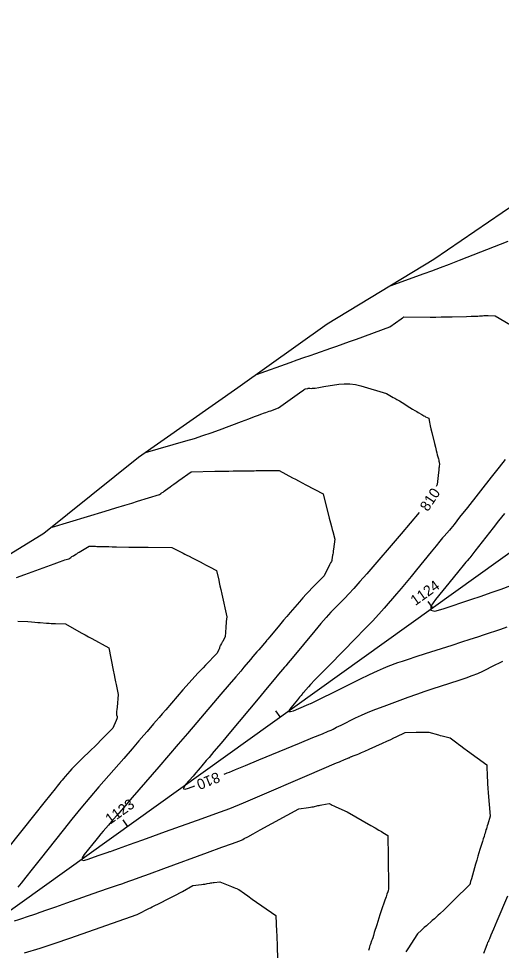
# Model space of a CAD drawing. Extents: x 2079879 to 2092887, y 778083 to 784051.
# Drawn here: x 2084202.5 to 2084331.2, y 781138.5 to 781386.8 of the extents above; entities that cross this region are included whole.
import ezdxf

# ---------------------------------------------------------------- set-up
doc = ezdxf.new("R2010")
doc.units = 0
for name, color, linetype in [('DT_X_Contour_Major', 7, 'Continuous'), ('DT_X_Contour_Minor', 7, 'Continuous'), ('DT_X_TIN_Hull', 7, 'Continuous'), ('GE_X_CL_20', 7, 'Continuous')]:
    doc.layers.add(name, color=color, linetype=linetype)

msp = doc.modelspace()

# ---------------------------------------------------------------- linework, layer by layer
at = {"layer": 'DT_X_Contour_Major'}
for points in [[(2084236.35, 781271.19), (2084247.11, 781274.26), (2084249.4, 781274.94), (2084251.66, 781275.67), (2084253.89, 781276.43), (2084256.09, 781277.24), (2084261.92, 781279.45), (2084263.88, 781280.19), (2084265.39, 781280.76), (2084266.45, 781281.16), (2084267.06, 781281.38), (2084268.07, 781281.74), (2084268.46, 781281.88), (2084268.87, 781282.02), (2084269.29, 781282.17), (2084269.73, 781282.33), (2084271.83, 781283.06), (2084277.36, 781287.05), (2084278.01, 781287.52), (2084278.42, 781287.82), (2084278.61, 781287.95), (2084278.92, 781288.18), (2084279.58, 781288.27), (2084279.73, 781288.29), (2084279.87, 781288.3), (2084280.02, 781288.3), (2084280.17, 781288.29), (2084280.56, 781288.26), (2084280.88, 781288.29), (2084281.53, 781288.37), (2084282.52, 781288.52), (2084283.85, 781288.73), (2084287.83, 781289.37), (2084289.32, 781289.52), (2084290.8, 781289.5), (2084292.28, 781289.32), (2084293.74, 781288.96), (2084300.58, 781286.88), (2084302.39, 781285.87), (2084302.83, 781285.62), (2084303.37, 781285.3), (2084304, 781284.93), (2084304.73, 781284.48), (2084306.81, 781283.21), (2084307.53, 781282.77), (2084308.15, 781282.39), (2084308.65, 781282.09), (2084309.04, 781281.85), (2084309.95, 781281.32), (2084310.27, 781281.13), (2084310.55, 781280.97), (2084310.79, 781280.84), (2084310.99, 781280.73), (2084311.83, 781280.3), (2084312.02, 781279.21), (2084312.09, 781278.86), (2084312.22, 781278.3), (2084312.4, 781277.53), (2084312.65, 781276.53), (2084313.37, 781273.6), (2084313.63, 781272.59), (2084313.83, 781271.75), (2084314, 781271.08), (2084314.12, 781270.58), (2084314.4, 781269.49), (2084314.49, 781269.12), (2084314.56, 781268.83), (2084314.61, 781268.62), (2084314.64, 781268.5), (2084314.73, 781268.11), (2084314.63, 781267.5), (2084314.6, 781267.3), (2084314.56, 781266.96), (2084314.5, 781266.48), (2084314.43, 781265.86), (2084314.05, 781262.63), (2084313.83, 781262.07)], [(2084309.24, 781255.14), (2084304.46, 781249.47), (2084295.31, 781238.86), (2084293.47, 781236.75), (2084291.88, 781234.96), (2084290.53, 781233.49), (2084289.44, 781232.34), (2084286.84, 781229.7), (2084285.77, 781228.58), (2084284.52, 781227.2), (2084283.09, 781225.55), (2084281.48, 781223.63), (2084275.45, 781216.38), (2084274.38, 781215.1), (2084273.74, 781214.33), (2084273.52, 781214.07), (2084273.52, 781214.06), (2084273.39, 781213.92), (2084272.37, 781212.74), (2084271.81, 781212.08), (2084270.62, 781210.66), (2084268.8, 781208.48), (2084266.34, 781205.54), (2084258.96, 781196.69), (2084256.48, 781193.73), (2084254.59, 781191.46), (2084253.28, 781189.9), (2084252.55, 781189.04), (2084251.39, 781187.67), (2084250.91, 781187.12), (2084250.36, 781186.48), (2084249.73, 781185.74), (2084249.03, 781184.93), (2084247.04, 781182.63), (2084246.53, 781181.92), (2084246.48, 781181.53), (2084246.9, 781181.45), (2084247.78, 781181.69), (2084249.52, 781182.3)], [(2084257.32, 781185.4), (2084257.51, 781185.48), (2084257.72, 781185.57), (2084258.11, 781185.74), (2084258.74, 781186), (2084260.36, 781186.67), (2084262.96, 781187.74), (2084266.53, 781189.22), (2084277.37, 781193.69), (2084280.93, 781195.16), (2084283.48, 781196.21), (2084285.02, 781196.85), (2084285.55, 781197.07), (2084285.6, 781197.09), (2084285.8, 781197.19), (2084286.35, 781197.46), (2084287.26, 781197.91), (2084288.51, 781198.53), (2084292.34, 781200.42), (2084293.9, 781201.15), (2084295.69, 781201.92), (2084297.72, 781202.74), (2084299.99, 781203.59), (2084306.36, 781205.92), (2084308.69, 781206.76), (2084310.89, 781207.54), (2084312.97, 781208.24), (2084314.92, 781208.88), (2084319.95, 781210.48), (2084321.76, 781211.08), (2084323.41, 781211.69), (2084324.9, 781212.3), (2084326.23, 781212.92), (2084329.55, 781214.56), (2084330.68, 781215.12), (2084331.57, 781215.56)], [(2084332.86, 781152.9), (2084330.01, 781146.26), (2084329.07, 781144.08), (2084328.4, 781142.5), (2084327.98, 781141.52), (2084327.83, 781141.15), (2084327.78, 781140.96), (2084327.76, 781140.89), (2084327.73, 781140.82), (2084327.69, 781140.76), (2084327.65, 781140.69), (2084327.51, 781140.52), (2084327.37, 781140.16), (2084327.02, 781139.18), (2084326.46, 781137.59)]]:
    msp.add_lwpolyline(points, dxfattribs=at)
at = {"layer": 'DT_X_Contour_Minor'}
for points in [[(2084301.58, 781315.6), (2084310.64, 781318.87), (2084312.68, 781319.62), (2084314.93, 781320.46), (2084317.39, 781321.41), (2084320.05, 781322.45), (2084332.98, 781327.53)], [(2084265.91, 781291.97), (2084274.89, 781295.17), (2084276.76, 781295.84), (2084278.53, 781296.46), (2084280.2, 781297.05), (2084281.76, 781297.6), (2084285.78, 781299), (2084287.33, 781299.54), (2084288.99, 781300.13), (2084290.74, 781300.76), (2084292.58, 781301.43), (2084301.43, 781304.64), (2084304.45, 781306.8), (2084304.8, 781307.05), (2084305.02, 781307.2), (2084305.1, 781307.27), (2084305.22, 781307.35), (2084312.22, 781307.3), (2084313.71, 781307.3), (2084315.18, 781307.31), (2084316.63, 781307.33), (2084318.07, 781307.36), (2084321.86, 781307.46), (2084323.14, 781307.49), (2084324.15, 781307.52), (2084324.89, 781307.56), (2084325.35, 781307.58), (2084326.2, 781307.65), (2084326.53, 781307.68), (2084326.89, 781307.69), (2084327.26, 781307.7), (2084327.65, 781307.69), (2084329.54, 781307.65), (2084333.63, 781305.2)], [(2084332.2, 781269.31), (2084330.62, 781267.3), (2084328.51, 781264.61), (2084322.16, 781256.55), (2084320.07, 781253.91), (2084318.58, 781252.01), (2084317.68, 781250.88), (2084317.38, 781250.49), (2084315.96, 781248.91), (2084315.52, 781248.39), (2084314.79, 781247.51), (2084313.77, 781246.27), (2084312.46, 781244.67), (2084308.59, 781239.9), (2084307.17, 781238.16), (2084305.8, 781236.5), (2084304.49, 781234.94), (2084303.23, 781233.47), (2084299.94, 781229.66), (2084298.54, 781228.08), (2084296.8, 781226.21), (2084294.73, 781224.04), (2084292.33, 781221.58), (2084285.46, 781214.61), (2084283.18, 781212.29), (2084281.46, 781210.53), (2084280.32, 781209.33), (2084279.75, 781208.71), (2084278.46, 781207.16), (2084278.42, 781207.12), (2084278.23, 781206.89), (2084278.11, 781206.75), (2084277.84, 781206.43), (2084277.41, 781205.92), (2084276.83, 781205.22), (2084275.07, 781203.11), (2084274.62, 781202.47), (2084274.58, 781202.13), (2084274.96, 781202.09), (2084275.75, 781202.35), (2084279.29, 781203.81), (2084279.92, 781204.07), (2084280.3, 781204.23), (2084280.43, 781204.28), (2084280.44, 781204.29), (2084280.79, 781204.46), (2084281.84, 781204.98), (2084283.58, 781205.84), (2084286.02, 781207.05), (2084293.47, 781210.73), (2084296.03, 781211.98), (2084298.14, 781212.98), (2084299.8, 781213.72), (2084301.01, 781214.2), (2084303.62, 781215.16), (2084304.81, 781215.58), (2084306.42, 781216.12), (2084308.46, 781216.79), (2084310.93, 781217.58), (2084318.07, 781219.85), (2084320.61, 781220.67), (2084322.89, 781221.4), (2084324.91, 781222.06), (2084326.67, 781222.65), (2084331.01, 781224.1), (2084332.76, 781224.7)], [(2084211.45, 781251.28), (2084225.62, 781255.54), (2084228.44, 781256.39), (2084230.81, 781257.11), (2084232.73, 781257.7), (2084234.22, 781258.16), (2084240.09, 781259.99), (2084240.34, 781260.16), (2084240.39, 781260.19), (2084240.45, 781260.23), (2084240.5, 781260.27), (2084240.56, 781260.31), (2084240.71, 781260.42), (2084240.82, 781260.5), (2084241.02, 781260.64), (2084241.32, 781260.86), (2084241.72, 781261.15), (2084242.91, 781262), (2084243.39, 781262.35), (2084243.94, 781262.74), (2084244.55, 781263.18), (2084245.23, 781263.67), (2084248.54, 781266.06), (2084254.81, 781266.17), (2084256.13, 781266.19), (2084257.39, 781266.21), (2084258.58, 781266.23), (2084259.73, 781266.25), (2084262.69, 781266.29), (2084263.72, 781266.31), (2084264.6, 781266.32), (2084265.32, 781266.33), (2084265.88, 781266.34), (2084267.17, 781266.36), (2084267.67, 781266.36), (2084268.18, 781266.37), (2084268.72, 781266.37), (2084269.28, 781266.36), (2084271.94, 781266.34), (2084275.51, 781264.45), (2084276.31, 781264.04), (2084277.16, 781263.59), (2084278.08, 781263.11), (2084279.05, 781262.6), (2084283.74, 781260.16), (2084285.34, 781253.71), (2084285.66, 781252.44), (2084285.91, 781251.42), (2084286.11, 781250.63), (2084286.26, 781250.08), (2084286.79, 781248.07), (2084286.45, 781245.45), (2084286.38, 781244.92), (2084286.32, 781244.47), (2084286.27, 781244.09), (2084286.22, 781243.78), (2084286.05, 781242.53), (2084286.04, 781242.47), (2084286, 781242.38), (2084285.88, 781242.14), (2084285.68, 781241.74), (2084285.41, 781241.2), (2084283.92, 781238.31), (2084280.68, 781235), (2084279.95, 781234.25), (2084279.16, 781233.39), (2084278.32, 781232.45), (2084277.41, 781231.41), (2084274.91, 781228.5), (2084274.01, 781227.45), (2084273.17, 781226.47), (2084272.41, 781225.57), (2084271.72, 781224.74), (2084269.38, 781221.94), (2084268.97, 781221.44), (2084268.71, 781221.14), (2084268.63, 781221.03), (2084268.61, 781221.01), (2084266.51, 781218.59), (2084266.03, 781218.04), (2084265.51, 781217.43), (2084264.94, 781216.75), (2084264.31, 781216.01), (2084262.59, 781213.94), (2084261.72, 781212.9), (2084260.41, 781211.35), (2084258.65, 781209.29), (2084256.45, 781206.72), (2084250, 781199.16), (2084247.56, 781196.3), (2084245.06, 781193.38), (2084242.5, 781190.41), (2084239.89, 781187.38), (2084232.84, 781179.22), (2084230.47, 781176.46), (2084228.61, 781174.32), (2084227.29, 781172.79), (2084226.49, 781171.87), (2084225.06, 781170.22), (2084224.48, 781169.54), (2084223.83, 781168.76), (2084223.1, 781167.85), (2084222.29, 781166.83), (2084220.03, 781163.97), (2084219.44, 781163.08), (2084219.37, 781162.57), (2084219.81, 781162.43), (2084220.77, 781162.66), (2084224.02, 781163.79), (2084225.09, 781164.17), (2084225.87, 781164.44), (2084226.36, 781164.61), (2084226.57, 781164.68), (2084226.89, 781164.8), (2084227.04, 781164.85), (2084227.47, 781165.01), (2084229.15, 781165.62), (2084232.13, 781166.71), (2084233.57, 781167.22), (2084235.64, 781167.96), (2084238.34, 781168.93), (2084241.69, 781170.11), (2084251.45, 781173.57), (2084255.11, 781174.9), (2084258.79, 781176.31), (2084262.48, 781177.79), (2084266.18, 781179.35), (2084279.42, 781185.04), (2084287.27, 781188.42), (2084288.01, 781188.74), (2084288.61, 781188.99), (2084289.07, 781189.19), (2084289.4, 781189.33), (2084290.08, 781189.61), (2084290.31, 781189.7), (2084290.48, 781189.77), (2084290.6, 781189.82), (2084290.67, 781189.85), (2084290.77, 781189.9), (2084290.81, 781189.92), (2084290.86, 781189.94), (2084290.93, 781189.97), (2084291.01, 781190.01), (2084291.22, 781190.12), (2084291.33, 781190.17), (2084291.49, 781190.23), (2084291.71, 781190.32), (2084291.98, 781190.42), (2084292.78, 781190.71), (2084293.2, 781190.88), (2084293.88, 781191.17), (2084294.8, 781191.58), (2084295.98, 781192.11), (2084299.47, 781193.69), (2084300.68, 781194.24), (2084301.69, 781194.71), (2084302.5, 781195.09), (2084303.11, 781195.38), (2084305.51, 781196.55), (2084308.48, 781196.61), (2084309.08, 781196.62), (2084309.59, 781196.62), (2084310.03, 781196.63), (2084310.38, 781196.62), (2084311.83, 781196.6), (2084314.39, 781195.91), (2084314.91, 781195.77), (2084315.37, 781195.64), (2084315.77, 781195.54), (2084316.12, 781195.45), (2084317.57, 781195.07), (2084319.28, 781193.78), (2084319.74, 781193.44), (2084320.38, 781192.97), (2084321.2, 781192.37), (2084322.2, 781191.64), (2084327.33, 781187.92), (2084327.43, 781184.56), (2084327.46, 781183.76), (2084327.51, 781182.81), (2084327.59, 781181.7), (2084327.69, 781180.44), (2084328.2, 781174.19), (2084327.55, 781172.09), (2084327.41, 781171.66), (2084327.29, 781171.26), (2084327.18, 781170.89), (2084327.08, 781170.56), (2084326.83, 781169.72), (2084326.71, 781169.34), (2084326.56, 781168.84), (2084326.37, 781168.22), (2084326.14, 781167.47), (2084325.46, 781165.32), (2084325.2, 781164.47), (2084324.93, 781163.54), (2084324.63, 781162.54), (2084324.32, 781161.46), (2084323.47, 781158.47), (2084323.19, 781157.48), (2084322.99, 781156.78), (2084322.87, 781156.35), (2084322.83, 781156.2), (2084322.82, 781156.17), (2084322.82, 781156.16), (2084322.81, 781156.15), (2084322.81, 781156.13), (2084322.81, 781156.12), (2084322.79, 781156.05), (2084318.56, 781151.87), (2084317.71, 781151.03), (2084316.99, 781150.32), (2084316.39, 781149.74), (2084315.91, 781149.28), (2084314.8, 781148.23), (2084314.36, 781147.82), (2084313.88, 781147.38), (2084313.35, 781146.9), (2084312.78, 781146.39), (2084311.19, 781144.99), (2084310.65, 781144.51), (2084310.21, 781144.12), (2084309.88, 781143.82), (2084308.83, 781142.9), (2084306.27, 781138.88), (2084305.74, 781138.05)], [(2084331.99, 781254.94), (2084330.45, 781252.92), (2084329.02, 781251.08), (2084324.13, 781244.88), (2084323.27, 781243.79), (2084322.75, 781243.13), (2084322.58, 781242.91), (2084322.07, 781242.34), (2084321.75, 781241.96), (2084321.03, 781241.07), (2084319.88, 781239.67), (2084318.33, 781237.75), (2084313.62, 781231.95), (2084312.43, 781230.17), (2084312.37, 781229.16), (2084313.44, 781228.92), (2084315.66, 781229.47), (2084323.07, 781231.96), (2084325.83, 781232.89), (2084328.51, 781233.83), (2084331.14, 781234.77), (2084333.71, 781235.71)], [(2084201.96, 781237.84), (2084204.18, 781238.64), (2084210.05, 781240.79), (2084212, 781241.5), (2084213.46, 781242.02), (2084214.42, 781242.37), (2084214.88, 781242.53), (2084215.88, 781242.84), (2084216.45, 781243.22), (2084216.58, 781243.3), (2084216.75, 781243.41), (2084216.93, 781243.53), (2084217.15, 781243.66), (2084217.77, 781244.04), (2084218.03, 781244.2), (2084218.34, 781244.4), (2084218.72, 781244.63), (2084219.15, 781244.9), (2084221.3, 781246.23), (2084223, 781246.17), (2084223.36, 781246.16), (2084223.73, 781246.14), (2084224.09, 781246.13), (2084224.44, 781246.13), (2084225.39, 781246.11), (2084225.86, 781246.1), (2084226.55, 781246.08), (2084227.46, 781246.06), (2084228.59, 781246.04), (2084231.9, 781245.97), (2084233.16, 781245.95), (2084234.44, 781245.93), (2084235.75, 781245.91), (2084237.09, 781245.9), (2084243.39, 781245.85), (2084244.28, 781245.4), (2084244.75, 781245.16), (2084246.39, 781244.33), (2084246.81, 781244.11), (2084247.35, 781243.84), (2084247.99, 781243.51), (2084248.75, 781243.12), (2084250.92, 781242), (2084251.69, 781241.61), (2084252.35, 781241.27), (2084252.91, 781240.98), (2084253.37, 781240.74), (2084255.3, 781239.76), (2084255.88, 781237.15), (2084256.02, 781236.49), (2084256.2, 781235.66), (2084256.42, 781234.64), (2084256.69, 781233.44), (2084258, 781227.41), (2084257.88, 781226.16), (2084257.86, 781225.86), (2084257.82, 781225.49), (2084257.79, 781225.06), (2084257.74, 781224.56), (2084257.54, 781222.06), (2084257.02, 781221.03), (2084256.92, 781220.82), (2084256.81, 781220.62), (2084256.71, 781220.43), (2084256.61, 781220.25), (2084256.34, 781219.79), (2084256.26, 781219.64), (2084256.19, 781219.51), (2084256.15, 781219.4), (2084256.13, 781219.33), (2084256.1, 781219.17), (2084256.08, 781219.09), (2084256.04, 781218.97), (2084255.98, 781218.82), (2084255.89, 781218.63), (2084255.47, 781217.66), (2084252.38, 781214.47), (2084251.71, 781213.77), (2084251.03, 781213.05), (2084250.33, 781212.31), (2084249.62, 781211.54), (2084246.26, 781207.88), (2084241.75, 781202.6), (2084240.83, 781201.52), (2084239.98, 781200.53), (2084239.21, 781199.63), (2084238.52, 781198.83), (2084236.79, 781196.83), (2084235.91, 781195.81), (2084234.58, 781194.28), (2084232.79, 781192.22), (2084230.54, 781189.63), (2084223.94, 781182.04), (2084221.49, 781179.19), (2084219.08, 781176.32), (2084216.72, 781173.43), (2084214.4, 781170.52), (2084208.27, 781162.75), (2084206.18, 781160.09), (2084204.5, 781157.96), (2084203.23, 781156.35), (2084202.37, 781155.27)], [(2084202.37, 781226.25), (2084205.04, 781226.08), (2084206, 781226.02), (2084206.86, 781225.96), (2084207.64, 781225.9), (2084208.32, 781225.85), (2084210.01, 781225.72), (2084210.64, 781225.67), (2084211.24, 781225.63), (2084211.83, 781225.6), (2084212.4, 781225.57), (2084215, 781225.46), (2084218.62, 781223.46), (2084219.42, 781223.02), (2084220.26, 781222.56), (2084221.15, 781222.07), (2084222.09, 781221.56), (2084226.56, 781219.13), (2084227.77, 781213.11), (2084228.01, 781211.91), (2084228.22, 781210.89), (2084228.39, 781210.04), (2084228.53, 781209.37), (2084229.09, 781206.65), (2084228.76, 781203.29), (2084228.7, 781202.65), (2084228.66, 781202.16), (2084228.63, 781201.84), (2084228.62, 781201.68), (2084228.61, 781201.28), (2084228.82, 781200.82), (2084228.83, 781200.68), (2084228.79, 781200.45), (2084228.68, 781200.14), (2084228.52, 781199.75), (2084227.63, 781197.71), (2084225, 781194.99), (2084224.38, 781194.36), (2084223.65, 781193.64), (2084222.81, 781192.81), (2084221.86, 781191.89), (2084219.17, 781189.29), (2084218.23, 781188.37), (2084217.43, 781187.56), (2084216.75, 781186.86), (2084216.21, 781186.26), (2084214.95, 781184.81), (2084214.51, 781184.29), (2084214.12, 781183.83), (2084213.79, 781183.43), (2084213.51, 781183.09), (2084212.85, 781182.25), (2084212.29, 781181.55), (2084211.11, 781180.06), (2084209.3, 781177.79), (2084206.87, 781174.74), (2084199.56, 781165.57)], [(2084201.43, 781146.34), (2084202.58, 781146.68), (2084203.64, 781147.02), (2084204.61, 781147.35), (2084207.1, 781148.22), (2084208.31, 781148.65), (2084210.1, 781149.27), (2084212.45, 781150.09), (2084215.38, 781151.11), (2084223.95, 781154.1), (2084226.79, 781155.09), (2084228.9, 781155.82), (2084230.27, 781156.3), (2084230.9, 781156.52), (2084232.18, 781156.97), (2084232.4, 781157.05), (2084232.99, 781157.27), (2084234.66, 781157.88), (2084237.42, 781158.88), (2084241.24, 781160.27), (2084252.89, 781164.52), (2084256.73, 781165.92), (2084259.52, 781166.94), (2084261.24, 781167.58), (2084261.91, 781167.84), (2084262.27, 781168.02), (2084262.67, 781168.23), (2084263.58, 781168.73), (2084265, 781169.51), (2084266.94, 781170.57), (2084277.17, 781176.19), (2084279.76, 781176.54), (2084280.28, 781176.62), (2084280.72, 781176.69), (2084281.08, 781176.75), (2084281.36, 781176.81), (2084282.01, 781176.97), (2084282.28, 781177.03), (2084282.59, 781177.09), (2084282.94, 781177.16), (2084283.33, 781177.23), (2084285.27, 781177.57), (2084285.66, 781177.39), (2084285.81, 781177.32), (2084286.11, 781177.19), (2084286.54, 781177), (2084287.11, 781176.74), (2084290.09, 781175.39), (2084296.38, 781171.78), (2084297.59, 781171.08), (2084298.54, 781170.53), (2084299.22, 781170.13), (2084299.63, 781169.88), (2084300.94, 781169.07), (2084300.95, 781168.13), (2084300.95, 781167.71), (2084300.96, 781166.85), (2084300.98, 781165.57), (2084301, 781163.84), (2084301.13, 781154.8), (2084301.03, 781154.42), (2084301.01, 781154.34), (2084300.99, 781154.27), (2084300.97, 781154.21), (2084300.95, 781154.15), (2084300.9, 781154.01), (2084300.83, 781153.84), (2084300.69, 781153.41), (2084300.46, 781152.73), (2084300.14, 781151.8), (2084299.19, 781148.98), (2084298.84, 781147.96), (2084298.53, 781147), (2084298.24, 781146.11), (2084297.98, 781145.29), (2084297.33, 781143.18), (2084297.11, 781142.45), (2084296.91, 781141.83), (2084296.74, 781141.33), (2084296.61, 781140.95), (2084296.29, 781140.08), (2084296.17, 781139.74), (2084296.05, 781139.35), (2084295.92, 781138.92), (2084295.79, 781138.45)], [(2084204.13, 781137.8), (2084208.25, 781139.04), (2084212.27, 781140.33), (2084216.18, 781141.66), (2084234.17, 781147.98), (2084234.35, 781148.08), (2084237.46, 781149.71), (2084237.65, 781149.81), (2084238.1, 781150.04), (2084238.82, 781150.4), (2084239.79, 781150.89), (2084242.75, 781152.38), (2084243.79, 781152.91), (2084244.71, 781153.38), (2084245.5, 781153.8), (2084246.17, 781154.16), (2084248.98, 781155.7), (2084251.28, 781156.01), (2084251.74, 781156.08), (2084252.15, 781156.14), (2084252.5, 781156.19), (2084252.79, 781156.24), (2084253.48, 781156.37), (2084253.75, 781156.41), (2084254.04, 781156.46), (2084254.34, 781156.5), (2084254.66, 781156.54), (2084256.17, 781156.72), (2084259.31, 781155.46), (2084259.9, 781155.22), (2084260.35, 781155.04), (2084260.66, 781154.92), (2084260.81, 781154.85), (2084261.19, 781154.7), (2084261.84, 781154.23), (2084262.13, 781154.03), (2084262.72, 781153.61), (2084263.61, 781152.98), (2084264.81, 781152.14), (2084271.07, 781147.72), (2084271.29, 781143.42), (2084271.33, 781142.46), (2084271.37, 781141.44), (2084271.42, 781140.35), (2084271.46, 781139.2), (2084271.64, 781133.67)]]:
    msp.add_lwpolyline(points, dxfattribs=at)
at = {"layer": 'DT_X_TIN_Hull'}
msp.add_lwpolyline([(2084420.64, 781401.06), (2084391.32, 781379.16), (2084366.83, 781361.2), (2084347.43, 781356.11), (2084344.84, 781360.3), (2084337.63, 781355.5), (2084342.14, 781349.52), (2084338.65, 781340.09), (2084313.15, 781322.64), (2084284.75, 781305.36), (2084260.97, 781288.46), (2084234.45, 781269.85), (2084209.3, 781249.55), (2084182.77, 781233.3), (2084158.56, 781216.56), (2084131.63, 781197.45), (2084106.47, 781178.42), (2084083.21, 781163.08), (2084059.54, 781146.11), (2084036.93, 781129.67)], dxfattribs=at)
at = {"layer": 'GE_X_CL_20'}
for p, q in [((2079923.52, 778084.44), (2085691.45, 782217.74)), ((2084312.87, 781229.84), (2084311.7, 781231.47)), ((2084272.23, 781200.72), (2084271.06, 781202.35)), ((2084231.59, 781171.6), (2084230.42, 781173.22))]:
    msp.add_line(p, q, dxfattribs=at)

# ---------------------------------------------------------------- texts
at = {"layer": 'DT_X_Contour_Major'}
for rotation, p in [(56.469, (2084311.59, 781255.28)), (201.6267, (2084255.5, 781186.07))]:
    msp.add_text('810', height=2.8, rotation=rotation, dxfattribs=at).set_placement(p)
at = {"layer": 'GE_X_CL_20'}
for s, p in [('1124', (2084308.24, 781230.22)), ('1123', (2084226.92, 781171.94))]:
    msp.add_text(s, height=2.8, rotation=35.6254, dxfattribs=at).set_placement(p)

doc.saveas('drawing.dxf')
